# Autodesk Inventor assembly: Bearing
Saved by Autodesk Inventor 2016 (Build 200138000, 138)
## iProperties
Created: 2015-08
Part Number: Bearing
Document SubType Name: Assembly
Designer: Ugljesa
Mass: 72.9462 g
Surface Area: 85.1408 cm^2
Volume: 9.29251 cm^3
Density: 7.85 g/cm^3
ClientObjectVersion: 1
Author: Ugljesa
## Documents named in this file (2)
- C:\Users\Ugljesa\Desktop\Turbokompr\Assembly1\Design Accelerator\Bearing2.iam
- C:\Users\Ugljesa\Documents\Inventor\Content Center Files\R2016\en-US\BS 292 (V)\BS 292_ Part 1 - N 1005 - 25 x 47 x 12.ipt
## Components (1 placed, 1 different names)
1. BS 292: Part 1 (V) (Metric) N 1005 - 25 x 47 x 12:1
